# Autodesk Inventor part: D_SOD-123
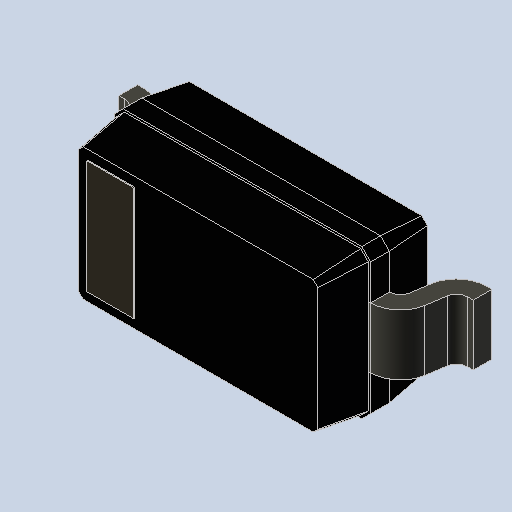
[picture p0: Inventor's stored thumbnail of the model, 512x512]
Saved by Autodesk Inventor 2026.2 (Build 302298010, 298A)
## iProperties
Created: 2026-10
Part Number: D_SOD-123
Material: Générique
Document SubType Name: Modeling
Designer: mel
Density: 1 g/cm^3
Appearance: Par défaut
Author: mel
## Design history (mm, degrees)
feature "Base1"
node "Solide1"
